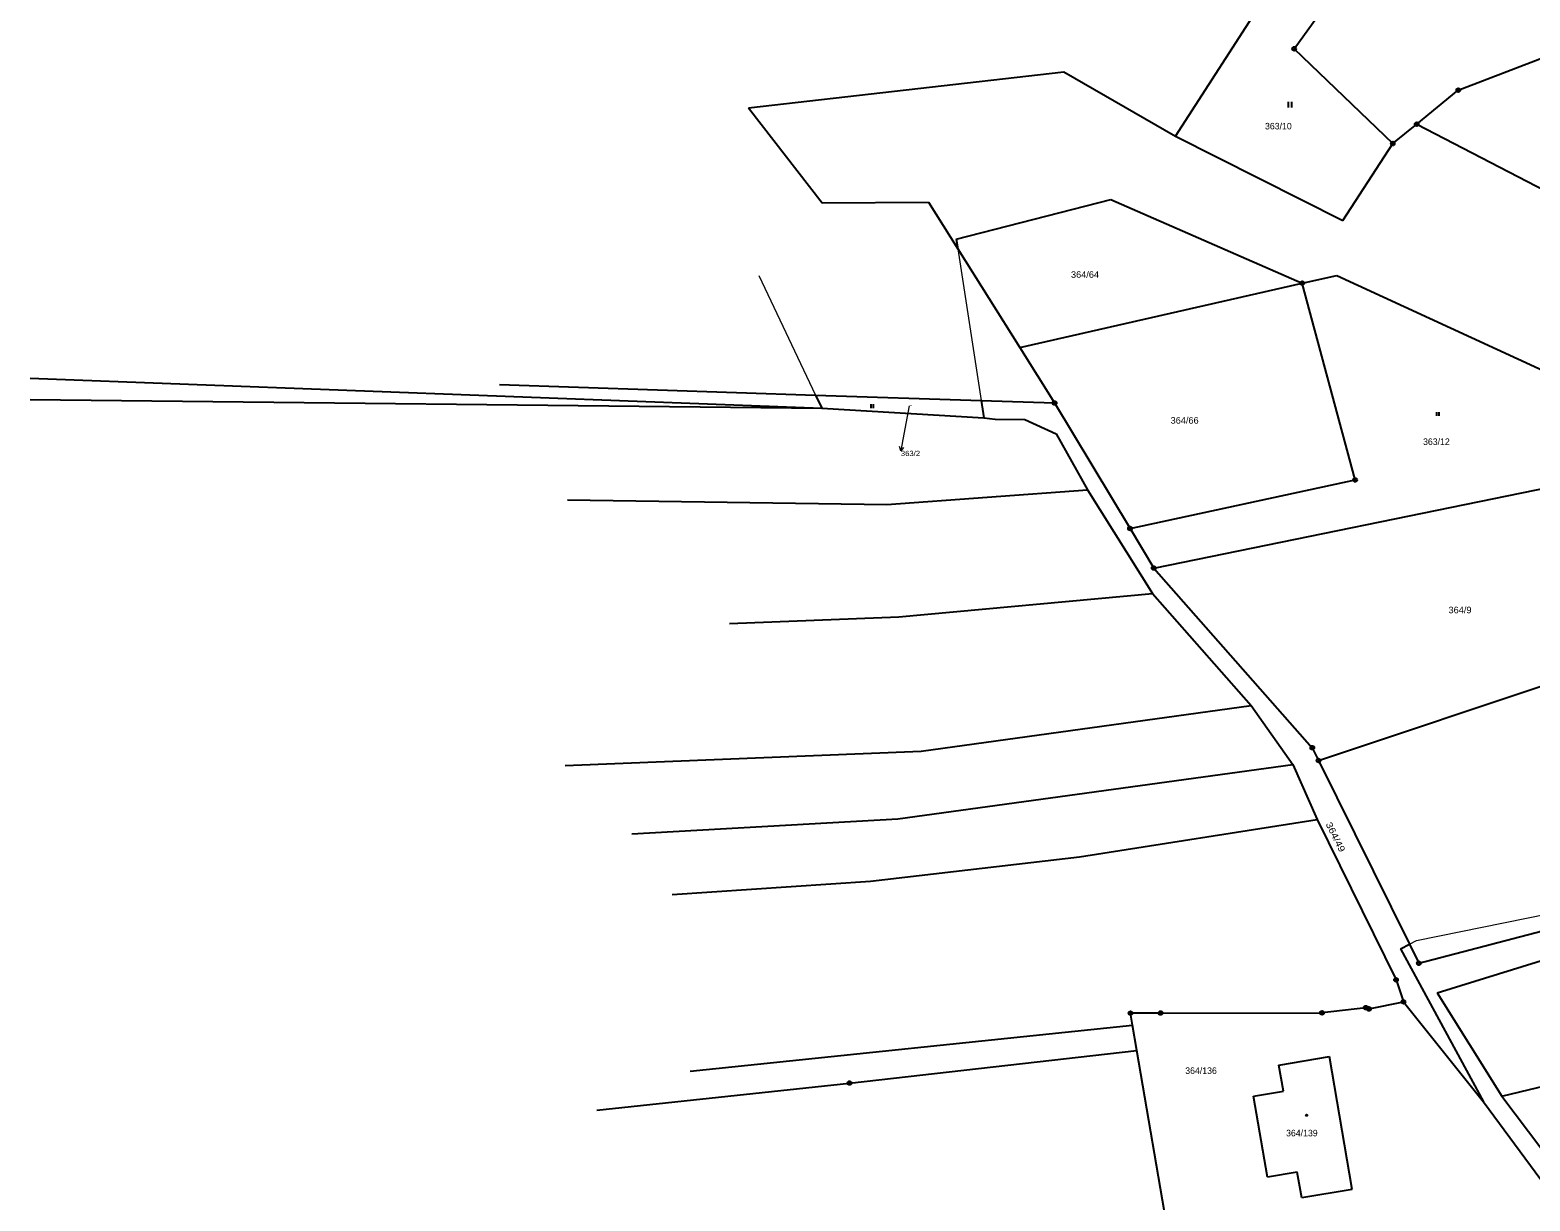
# Model space of a CAD drawing. Extents: x -592965 to -592390, y -1145071 to -1144631.
# Drawn here: x -592964.6 to -592769.5, y -1144987.4 to -1144835.1 of the extents above; entities that cross this region are included whole.
import ezdxf

# ---------------------------------------------------------------- set-up
doc = ezdxf.new("R2010")
doc.units = 0
doc.header["$LTSCALE"] = 0.17
doc.layers.add('4', color=7, linetype='Continuous', lineweight=25)

msp = doc.modelspace()

# ---------------------------------------------------------------- linework, layer by layer
at = {"layer": '4'}
for p, q in [((-592815.6, -1144848.96), (-592792.06, -1144812.47)), ((-592800.14, -1144837.58), (-592784.93, -1144816.46)), ((-592800.14, -1144837.58), (-592787.3, -1144849.91)), ((-592778.79, -1144842.96), (-592761.54, -1144836.35)), ((-592871.16, -1144845.26), (-592830.09, -1144840.56)), ((-592830.09, -1144840.56), (-592815.6, -1144848.96)), ((-592784.2, -1144847.38), (-592778.79, -1144842.96)), ((-592871.16, -1144845.26), (-592861.55, -1144857.62)), ((-592800.938, -1144844.462), (-592800.938, -1144845.212)), ((-592800.428, -1144845.212), (-592800.428, -1144844.462)), ((-592787.3, -1144849.91), (-592784.2, -1144847.38)), ((-592784.2, -1144847.38), (-592760.83, -1144859.48)), ((-592815.6, -1144848.96), (-592793.81, -1144859.93)), ((-592793.81, -1144859.93), (-592787.3, -1144849.91)), ((-592844.11, -1144862.33), (-592823.99, -1144857.18)), ((-592823.99, -1144857.18), (-592799.09, -1144868.07)), ((-592861.55, -1144857.62), (-592847.74, -1144857.51)), ((-592847.74, -1144857.51), (-592843.91, -1144863.6)), ((-592799.09, -1144868.07), (-592794.59, -1144867.05)), ((-592794.59, -1144867.05), (-592749.94, -1144887.66)), ((-592835.84, -1144876.43), (-592799.09, -1144868.07)), ((-592835.84, -1144876.43), (-592831.31, -1144883.65)), ((-592964.6, -1144880.43), (-592861.6, -1144884.33)), ((-592903.55, -1144881.25), (-592862.41, -1144882.62)), ((-592862.41, -1144882.62), (-592861.6, -1144884.33)), ((-592862.41, -1144882.62), (-592840.87, -1144883.34)), ((-592964.62, -1144883.19), (-592861.6, -1144884.33)), ((-592861.6, -1144884.33), (-592840.52, -1144885.6)), ((-592855.241, -1144883.783), (-592855.241, -1144884.308)), ((-592854.883, -1144884.308), (-592854.883, -1144883.783)), ((-592840.87, -1144883.34), (-592840.52, -1144885.6)), ((-592840.87, -1144883.34), (-592831.31, -1144883.65)), ((-592831.31, -1144883.65), (-592821.5, -1144899.97)), ((-592835.18, -1144885.81), (-592831.1, -1144887.68)), ((-592781.646, -1144884.83), (-592781.646, -1144885.34)), ((-592781.298, -1144885.34), (-592781.298, -1144884.83)), ((-592831.1, -1144887.68), (-592827.02, -1144894.95)), ((-592818.42, -1144905.12), (-592751.2, -1144891.37)), ((-592894.69, -1144896.26), (-592853.15, -1144896.85)), ((-592853.15, -1144896.85), (-592827.02, -1144894.95)), ((-592827.02, -1144894.95), (-592818.59, -1144908.43)), ((-592821.5, -1144899.97), (-592818.42, -1144905.12)), ((-592818.42, -1144905.12), (-592797.79, -1144928.49)), ((-592851.56, -1144911.46), (-592818.59, -1144908.43)), ((-592818.59, -1144908.43), (-592805.75, -1144922.99)), ((-592873.61, -1144912.32), (-592851.56, -1144911.46)), ((-592796.97, -1144930.15), (-592757.53, -1144916.96)), ((-592848.69, -1144928.94), (-592805.75, -1144922.99)), ((-592895.01, -1144930.8), (-592848.69, -1144928.94)), ((-592851.69, -1144937.74), (-592800.3, -1144930.66)), ((-592886.3, -1144939.67), (-592851.69, -1144937.74)), ((-592828.08, -1144942.7), (-592797.15, -1144937.83)), ((-592797.15, -1144937.83), (-592786.89, -1144958.67)), ((-592855.28, -1144945.85), (-592828.08, -1144942.7)), ((-592881.05, -1144947.57), (-592855.28, -1144945.85)), ((-592783.93, -1144956.52), (-592752.74, -1144948.34)), ((-592786.3, -1144954.64), (-592775.53, -1144974.54)), ((-592781.54, -1144960.35), (-592765.56, -1144955.44)), ((-592786.89, -1144958.67), (-592785.92, -1144961.54)), ((-592781.54, -1144960.35), (-592773.14, -1144973.83)), ((-592790.83, -1144962.3), (-592796.52, -1144962.97)), ((-592790.41, -1144962.46), (-592790.83, -1144962.3)), ((-592790.41, -1144962.46), (-592785.92, -1144961.54)), ((-592785.92, -1144961.54), (-592775.53, -1144974.54)), ((-592878.71, -1144970.56), (-592821.16, -1144964.57)), ((-592817.52, -1144963), (-592821.43, -1144963.01)), ((-592821.16, -1144964.57), (-592821.43, -1144963.01)), ((-592820.6, -1144967.86), (-592821.16, -1144964.57)), ((-592817.52, -1144963), (-592796.52, -1144962.97)), ((-592773.14, -1144973.83), (-592731.82, -1144963.8)), ((-592858, -1144972.1), (-592820.6, -1144967.86)), ((-592815.57, -1144997.13), (-592820.6, -1144967.86)), ((-592802.12, -1144969.76), (-592795.55, -1144968.64)), ((-592801.54, -1144973.17), (-592802.12, -1144969.76)), ((-592792.61, -1144985.95), (-592795.55, -1144968.64)), ((-592890.86, -1144975.63), (-592858, -1144972.1)), ((-592805.44, -1144973.83), (-592801.54, -1144973.17)), ((-592803.63, -1144984.35), (-592805.44, -1144973.83)), ((-592775.53, -1144974.54), (-592766.72, -1144986.47)), ((-592799.76, -1144983.69), (-592803.63, -1144984.35)), ((-592799.16, -1144987.04), (-592799.76, -1144983.69)), ((-592792.61, -1144985.95), (-592799.16, -1144987.04))]:
    msp.add_line(p, q, dxfattribs=at)
at = {"layer": '4', "lineweight": 13}
for p, q in [((-592843.91, -1144863.6), (-592840.87, -1144883.34)), ((-592869.8, -1144867.05), (-592862.41, -1144882.62))]:
    msp.add_line(p, q, dxfattribs=at)
at = {"layer": '4'}
for points in [[(-592844.11, -1144862.33), (-592843.91, -1144863.6), (-592835.84, -1144876.43)], [(-592821.5, -1144899.97), (-592792.2, -1144893.66), (-592799.09, -1144868.07)], [(-592840.52, -1144885.6), (-592839.06, -1144885.74), (-592835.18, -1144885.81)], [(-592805.75, -1144922.99), (-592800.3, -1144930.66), (-592797.15, -1144937.83)], [(-592797.79, -1144928.49), (-592796.97, -1144930.15), (-592785.15, -1144954.05)], [(-592786.3, -1144954.64), (-592785.15, -1144954.05), (-592783.93, -1144956.52)], [(-592773.14, -1144973.83), (-592764.58, -1144985.13), (-592715.69, -1144973.75)]]:
    msp.add_lwpolyline(points, dxfattribs=at)
at = {"layer": '4', "lineweight": 13}
for points in [[(-592850.23, -1144884.02), (-592851.045, -1144888.395), (-592851.32, -1144889.87)], [(-592850.982, -1144889.424), (-592851.32, -1144889.87), (-592851.474, -1144889.332)], [(-592785.15, -1144954.05), (-592784.23, -1144953.58), (-592695.58, -1144935.57)]]:
    msp.add_lwpolyline(points, dxfattribs=at)
at = {"layer": '4'}
for centre, radius in [((-592800.14, -1144837.58), 0.25), ((-592800.14, -1144837.58), 0.0164), ((-592778.79, -1144842.96), 0.25), ((-592778.79, -1144842.96), 0.0164), ((-592784.2, -1144847.38), 0.25), ((-592784.2, -1144847.38), 0.0164), ((-592787.3, -1144849.91), 0.25), ((-592787.3, -1144849.91), 0.0164), ((-592799.09, -1144868.07), 0.25), ((-592799.09, -1144868.07), 0.0164), ((-592831.31, -1144883.65), 0.25), ((-592831.31, -1144883.65), 0.0164), ((-592792.2, -1144893.66), 0.25), ((-592792.2, -1144893.66), 0.0164), ((-592821.5, -1144899.97), 0.25), ((-592821.5, -1144899.97), 0.0164), ((-592818.42, -1144905.12), 0.25), ((-592818.42, -1144905.12), 0.0164), ((-592797.79, -1144928.49), 0.25), ((-592797.79, -1144928.49), 0.0164), ((-592796.97, -1144930.15), 0.25), ((-592796.97, -1144930.15), 0.0164), ((-592783.93, -1144956.52), 0.25), ((-592783.93, -1144956.52), 0.0164), ((-592786.89, -1144958.67), 0.25), ((-592786.89, -1144958.67), 0.0164), ((-592796.52, -1144962.97), 0.25), ((-592790.83, -1144962.3), 0.25), ((-592790.83, -1144962.3), 0.0164), ((-592790.41, -1144962.46), 0.25), ((-592790.41, -1144962.46), 0.0164), ((-592785.92, -1144961.54), 0.25), ((-592785.92, -1144961.54), 0.0164), ((-592821.43, -1144963.01), 0.25), ((-592821.43, -1144963.01), 0.0164), ((-592817.52, -1144963), 0.25), ((-592817.52, -1144963), 0.0164), ((-592796.52, -1144962.97), 0.0164), ((-592858, -1144972.1), 0.25), ((-592858, -1144972.1), 0.0164), ((-592798.53, -1144976.29), 0.0875)]:
    msp.add_circle(centre, radius, dxfattribs=at)

# ---------------------------------------------------------------- texts
for s, p in [('363/10', (-592803.94, -1144848.07)), ('363/12', (-592783.374, -1144889.11)), ('364/136', (-592814.316, -1144970.915)), ('364/139', (-592801.196, -1144979.035))]:
    msp.add_text(s, height=0.85, dxfattribs=at).set_placement(p)
for s, height, width, p in [('364/64', 0.85, 1.05, (-592829.18, -1144867.37)), ('363/2', 0.1, 1.25, (-592850.23, -1144884.02)), ('364/66', 0.85, 1.05, (-592816.22, -1144886.34)), ('363/2', 0.68, 1.1, (-592851.319, -1144890.55)), ('364/9', 0.85, 1.05, (-592780.06, -1144911))]:
    msp.add_text(s, height=height, dxfattribs=dict(at, width=width)).set_placement(p)
at = {"layer": '4', "width": 1.2}
msp.add_text('364/49', height=0.85, rotation=296.55, dxfattribs=at).set_placement((-592796.07, -1144938.43))

doc.saveas('drawing.dxf')
